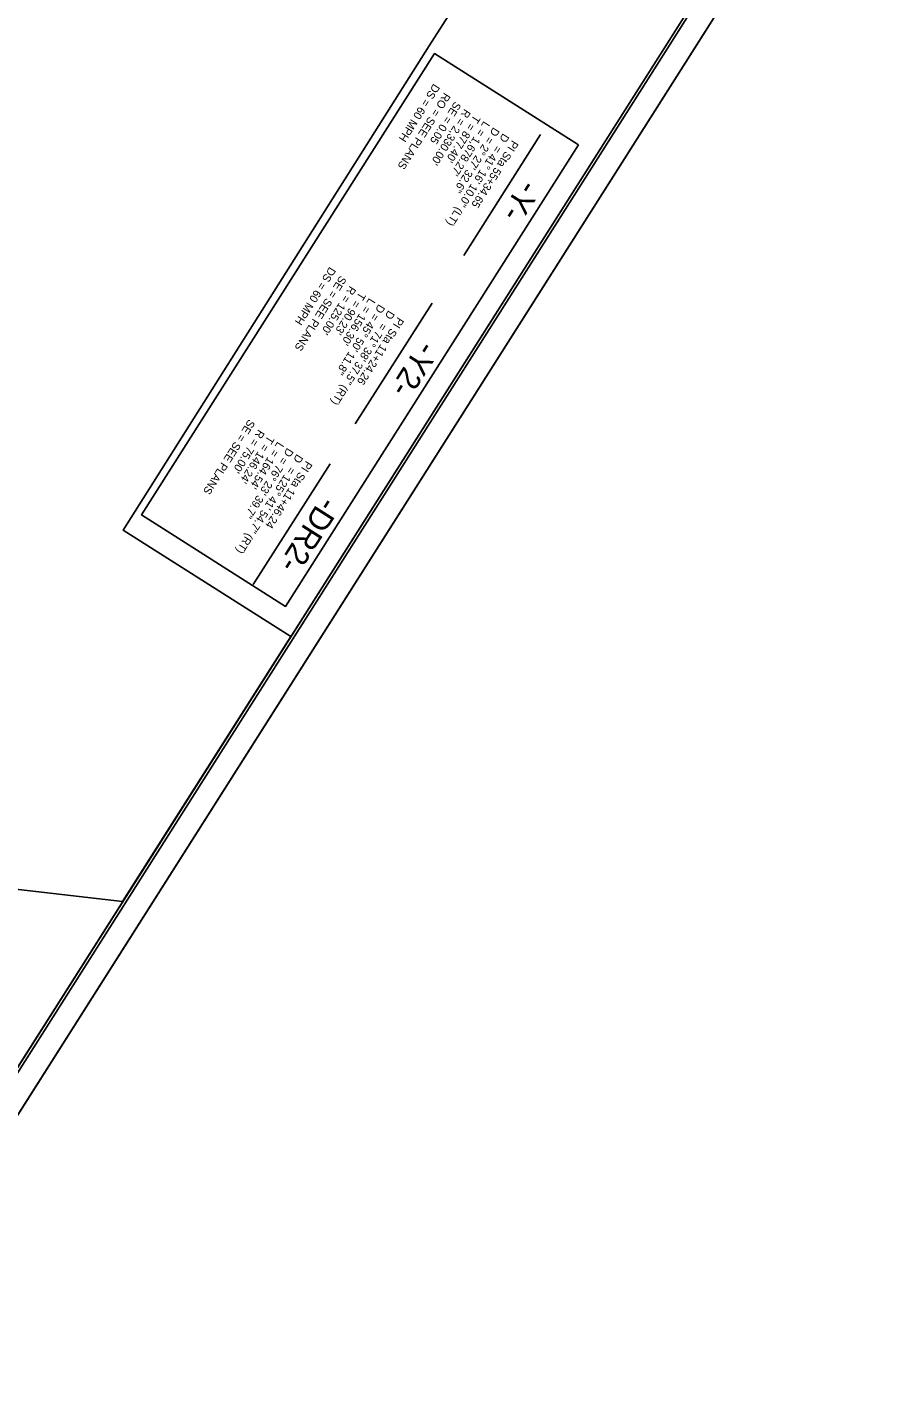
# Model space of a CAD drawing. Extents: x 1780138 to 1782093, y 811157 to 813450.
# Drawn here: x 1781286 to 1782026, y 811322 to 812514 of the extents above; entities that cross this region are included whole.
import ezdxf

# ---------------------------------------------------------------- set-up
doc = ezdxf.new("R2010")
doc.units = 0
for name, color, linetype in [('Prop Easement Aerial Utility', 7, 'Continuous'), ('Prop Easement Aerial Utility Station Offsets', 7, 'Continuous'), ('Prop Easement Permanent Utility', 7, 'Continuous'), ('Prop Easement Temporary Drainage', 7, 'Continuous'), ('Prop Easement Temporary Utility', 7, 'Continuous'), ('Prop ROW CA Lines', 7, 'Continuous'), ('Prop ROW Marker CELL', 7, 'Continuous'), ('Prop ROW RW CA Lines', 7, 'Continuous'), ('Prop ROW Station Offsets', 7, 'Continuous')]:
    doc.layers.add(name, color=color, linetype=linetype)

msp = doc.modelspace()

# ---------------------------------------------------------------- linework, layer by layer
at = {"layer": 'Prop Easement Aerial Utility'}
msp.add_line((1781124.1, 811321.9), (1782026.2, 812743.3), dxfattribs=at)
at = {"layer": 'Prop Easement Permanent Utility'}
msp.add_lwpolyline([(1781004.7, 813135.2), (1780254.5, 811953.1), (1780962.5, 811503.8), (1781063.9, 811663.6), (1781242.5, 811550.3), (1781891.2, 812572.6)], close=True, dxfattribs=at)
at = {"layer": 'Prop Easement Temporary Drainage'}
for points in [[(1781114.3, 811348.3), (1781918, 812614.8), (1781031.5, 813177.4), (1780227.7, 811910.9)], [(1781031.5, 813177.4), (1781918, 812614.8), (1781221.5, 811517.2), (1781094.8, 811597.6), (1780987.6, 811428.7), (1780227.7, 811910.9)]]:
    msp.add_lwpolyline(points, close=True, dxfattribs=at)
at = {"layer": 'Prop Easement Temporary Utility'}
msp.add_lwpolyline([(1781918, 812614.8), (1781031.5, 813177.4), (1780227.7, 811910.9), (1780935.7, 811461.6), (1781063.9, 811663.6), (1781242.5, 811550.3)], close=True, dxfattribs=at)
at = {"layer": 'Prop ROW CA Lines'}
msp.add_lwpolyline([(1781101.7, 813330), (1780199.6, 811908.6), (1781124.1, 811321.9), (1782026.2, 812743.3)], close=True, dxfattribs=at)
at = {"layer": 'Prop ROW Marker CELL'}
msp.add_lwpolyline([(1781516.2, 811981.6), (1781369.5, 812074.6), (1781637.4, 812498.2), (1781665.8, 812542.9), (1781507.5, 812669.1), (1780938.2, 813030.4), (1780382.1, 812154.2), (1780493.5, 812083.5), (1780398.6, 811861.6), (1781369, 811749.7)], close=True, dxfattribs=at)
at = {"layer": 'Prop ROW RW CA Lines'}
for p, q in [((1781734.7, 812420.7), (1781667.6, 812314.9)), ((1781639.8, 812273), (1781572.6, 812167.5)), ((1781550.6, 812132.5), (1781483.4, 812027))]:
    msp.add_line(p, q, dxfattribs=at)
msp.add_lwpolyline([(1781767.9, 812411.5), (1781511.6, 812007.8), (1781385.7, 812087.8), (1781642, 812491.4)], close=True, dxfattribs=at)
at = {"layer": 'Prop ROW Station Offsets'}
msp.add_lwpolyline([(1781111.6, 813308.3), (1780218.9, 811901.7), (1781109.7, 811336.4), (1782002.3, 812743)], close=True, dxfattribs=at)

# ---------------------------------------------------------------- texts
at = {"layer": 'Prop Easement Aerial Utility Station Offsets'}
for s, rotation, p in [('RO = SEE PLANS', 237.5579, (1781650.5, 812457.7)), ('DS = 60 MPH', 237.5579, (1781641.2, 812465.5)), ('SE = 0.05', 237.5579, (1781659.8, 812450)), ("R = 2,330.00'", 237.5579, (1781668.2, 812443.5)), ("T = 877.40'", 237.5579, (1781676.6, 812438.2)), ("L = 1,678.27'", 237.5579, (1781685.1, 812432.8)), ('D = 2%%d 27\' 32.6"', 237.5579, (1781693.5, 812427.4)), ('D', 237.5579, (1781701.9, 812422.1)), ('= 41%%d 16\' 10.0" (LT)', 237.5579, (1781695.4, 812411.5)), ('PI Sta 55+34.65', 237.5579, (1781710, 812416.1)), ('DS = 60 MPH', 237.5579, (1781550.2, 812305.3)), ('SE = SEE PLANS', 237.5579, (1781559.5, 812297.6)), ("R = 125.00'", 237.7399, (1781567.9, 812288.7)), ("T = 90.23'", 237.7399, (1781576.3, 812283.3)), ("L = 156.30'", 237.7399, (1781584.8, 812278)), ('D = 45%%d 50\' 11.8"', 237.7399, (1781593.2, 812272.7)), ('D', 237.7399, (1781601.7, 812267.3)), ('= 71%%d 38\' 37.5" (RT)', 237.7399, (1781595.1, 812256.3)), ('PI Sta 11+24.26', 237.7399, (1781609.8, 812261.4)), ('SE = SEE PLANS', 237.5579, (1781479.5, 812172)), ("R = 75.00'", 237.5444, (1781487.9, 812163.1)), ("T = 146.24'", 237.5444, (1781496.3, 812157.7)), ('D = 76%%d 23\' 39.7"', 237.5444, (1781513.2, 812147)), ("L = 164.54'", 237.5444, (1781504.7, 812152.4)), ('PI Sta 11+46.24', 237.5444, (1781529.7, 812135.7)), ('D', 237.5444, (1781521.6, 812141.6)), ('= 125%%d 41\' 54.7" (RT)', 237.5444, (1781515, 812130.6))]:
    msp.add_text(s, height=7, rotation=rotation, dxfattribs=at).set_placement(p)
at = {"layer": 'Prop ROW RW CA Lines'}
for s, p in [('-Y-', (1781718.8, 812382.2)), ('-Y2-', (1781629.8, 812241.3)), ('-DR2-', (1781543.4, 812105.1))]:
    msp.add_text(s, height=20, rotation=237.5186, dxfattribs=at).set_placement(p)

doc.saveas('drawing.dxf')
